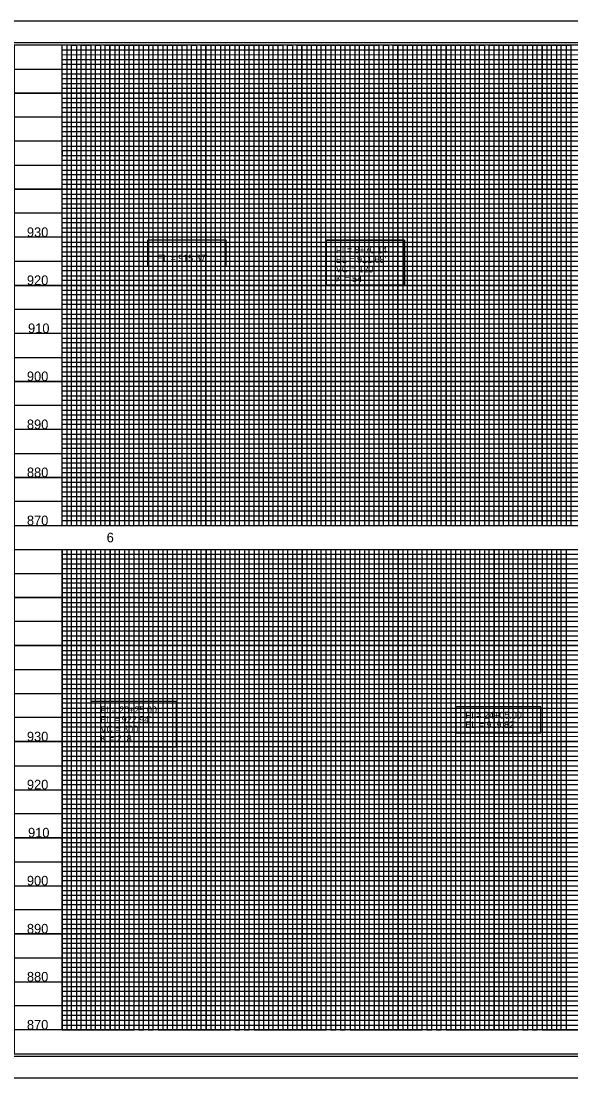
# Model space of a CAD drawing. Extents: x 1648157 to 1650776, y 832691 to 834781.
# Drawn here: x 1649037 to 1649609, y 832691 to 833791 of the extents above; entities that cross this region are included whole.
import ezdxf

# ---------------------------------------------------------------- set-up
doc = ezdxf.new("R2010")
doc.units = 0
for name, color, linetype in [('Exist Vertical Profile Horizontal Axis Label Major', 7, 'Continuous'), ('Exist Vertical Profile Vertical Axis Label', 7, 'Continuous'), ('Prop Grid Mask', 7, 'Continuous'), ('Prop Vertical Profile Curve Label', 7, 'Continuous'), ('Prop VPI Label', 7, 'Continuous'), ('Sheet Cutting Line CELL', 7, 'Continuous'), ('Sheet DOT Grid CELL', 7, 'Continuous'), ('Sheet Layout Profile Border Port 2', 7, 'Continuous'), ('Sheet Plot Border Inside CELL', 7, 'Continuous'), ('Sheet Plot Border Outside CELL', 7, 'Continuous'), ('Sheet Profile CELL', 7, 'Continuous'), ('Sheet Profile Grid Major CELL', 7, 'Continuous'), ('Sheet Profile Grid Middle CELL', 7, 'Continuous'), ('Sheet Profile Grid Minor CELL', 7, 'Continuous')]:
    doc.layers.add(name, color=color, linetype=linetype)

msp = doc.modelspace()

# ---------------------------------------------------------------- linework, layer by layer
at = {"layer": 'Prop Grid Mask'}
for points in [[(1649168.2, 833563), (1649168.2, 833536), (1649250.2, 833536), (1649250.2, 833563)], [(1649354.3, 833563.1), (1649436, 833563.1), (1649436, 833516.1), (1649354.3, 833516.1)], [(1649354.3, 833563.1), (1649354.3, 833516.1), (1649436, 833516.1), (1649436, 833563.1)], [(1649109.3, 833082.7), (1649109.3, 833035.7), (1649198.5, 833035.7), (1649198.5, 833082.7)], [(1649489.3, 833077.1), (1649489.3, 833050.1), (1649577.8, 833050.1), (1649577.8, 833077.1)]]:
    msp.add_lwpolyline(points, close=True, dxfattribs=at)
at = {"layer": 'Sheet Cutting Line CELL'}
for p, q in [((1650546.3, 833791), (1648862.3, 833791)), ((1648862.3, 832691), (1650546.3, 832691))]:
    msp.add_line(p, q, dxfattribs=at)
at = {"layer": 'Sheet DOT Grid CELL'}
for p, q in [((1649079.3, 833266), (1649079.3, 833766)), ((1649129.3, 833266), (1649129.3, 833766)), ((1649179.3, 833266), (1649179.3, 833766)), ((1649229.3, 833266), (1649229.3, 833766)), ((1649279.3, 833266), (1649279.3, 833766)), ((1649329.3, 833266), (1649329.3, 833766)), ((1649379.3, 833266), (1649379.3, 833766)), ((1649429.3, 833266), (1649429.3, 833766)), ((1649479.3, 833266), (1649479.3, 833766)), ((1649529.3, 833266), (1649529.3, 833766)), ((1649579.3, 833266), (1649579.3, 833766)), ((1650329.2, 833716), (1649029.3, 833716)), ((1650329.2, 833666), (1649029.3, 833666)), ((1650329.3, 833616), (1649029.3, 833616)), ((1650529.3, 833566), (1649029.3, 833566)), ((1650529.3, 833516), (1649029.3, 833516)), ((1650529.3, 833466), (1649029.3, 833466)), ((1650529.3, 833416), (1649029.3, 833416)), ((1650529.3, 833366), (1649029.3, 833366)), ((1650529.3, 833316), (1649029.3, 833316)), ((1649029.3, 833241), (1650529.2, 833241)), ((1649079.3, 833241), (1649079.3, 832741)), ((1649129.3, 833241), (1649129.3, 832741)), ((1649179.3, 833241), (1649179.3, 832741)), ((1649229.3, 833241), (1649229.3, 832741)), ((1649279.3, 833241), (1649279.3, 832741)), ((1649329.3, 833241), (1649329.3, 832741)), ((1649379.3, 833241), (1649379.3, 832741)), ((1649429.3, 833241), (1649429.3, 832741)), ((1649479.3, 833241), (1649479.3, 832741)), ((1649529.3, 833241), (1649529.3, 832741)), ((1649579.3, 833241), (1649579.3, 832741)), ((1649029.3, 833191), (1650529.2, 833191)), ((1649029.3, 833141), (1650529.2, 833141)), ((1649029.3, 833091), (1650529.2, 833091)), ((1649029.3, 833041), (1650529.2, 833041)), ((1649029.3, 832991), (1650529.2, 832991)), ((1649029.3, 832941), (1650529.2, 832941)), ((1649029.3, 832891), (1650529.2, 832891)), ((1649029.3, 832841), (1650529.2, 832841)), ((1649029.3, 832791), (1650529.2, 832791))]:
    msp.add_line(p, q, dxfattribs=at)
at = {"layer": 'Sheet Layout Profile Border Port 2'}
msp.add_lwpolyline([(1649079.3, 833241), (1650479.3, 833241), (1650479.3, 832741), (1649079.3, 832741)], close=True, dxfattribs=at)
at = {"layer": 'Sheet Plot Border Inside CELL'}
msp.add_lwpolyline([(1648875.3, 832713.5), (1650541.8, 832713.5), (1650541.8, 833768.6), (1648875.3, 833768.6)], close=True, dxfattribs=at)
at = {"layer": 'Sheet Plot Border Outside CELL'}
msp.add_lwpolyline([(1648862.3, 832691), (1650546.3, 832691), (1650546.3, 833791), (1648862.3, 833791)], close=True, dxfattribs=at)
at = {"layer": 'Sheet Profile CELL'}
for p, q in [((1649029.3, 833266), (1650529.3, 833266)), ((1649029.3, 833241), (1650529.3, 833241)), ((1650529.3, 832741), (1649029.3, 832741)), ((1649029.3, 832716), (1650529.3, 832716))]:
    msp.add_line(p, q, dxfattribs=at)
msp.add_lwpolyline([(1650529.3, 833766), (1649029.3, 833766), (1649029.3, 832716), (1650529.3, 832716)], close=True, dxfattribs=at)
msp.add_lwpolyline([(1649066.8, 832716), (1649066.8, 832716)], dxfattribs=at)
at = {"layer": 'Sheet Profile Grid Major CELL'}
msp.add_line((1649529.3, 833241), (1649579.3, 833241), dxfattribs=at)
for points in [[(1649079.2, 833766), (1649079.2, 833266), (1649129.2, 833266), (1649129.2, 833766), (1649179.2, 833766), (1649179.2, 833266), (1649229.2, 833266), (1649229.2, 833766), (1649279.2, 833766), (1649279.2, 833266), (1649329.2, 833266), (1649329.2, 833766), (1649379.2, 833766), (1649379.2, 833266), (1649429.2, 833266), (1649429.2, 833766), (1649479.2, 833766), (1649479.2, 833266), (1649529.2, 833266), (1649529.2, 833766), (1649579.2, 833766), (1649579.2, 833266), (1649629.2, 833266)], [(1649029.2, 833716), (1650329.2, 833716)], [(1650329.2, 833666), (1649029.2, 833666), (1649029.2, 833616), (1650329.2, 833616)], [(1650529.2, 833566), (1649029.2, 833566), (1649029.2, 833516), (1650529.2, 833516)], [(1650529.2, 833466), (1649029.2, 833466), (1649029.2, 833416), (1650529.2, 833416)], [(1650529.2, 833366), (1649029.2, 833366), (1649029.2, 833366), (1649029.2, 833316), (1650529.2, 833316)], [(1649079.3, 833241), (1649079.3, 832741), (1649129.3, 832741), (1649129.3, 833241), (1649179.3, 833241), (1649179.3, 832741), (1649229.3, 832741), (1649229.3, 833241), (1649279.3, 833241), (1649279.3, 832741), (1649329.3, 832741), (1649329.3, 833241), (1649379.3, 833241), (1649379.3, 832741), (1649429.3, 832741), (1649429.3, 833241), (1649479.3, 833241), (1649479.3, 832741), (1649529.3, 832741), (1649529.3, 833241), (1649579.3, 833241), (1649579.3, 832741), (1649629.3, 832741)], [(1650529.3, 833191), (1649029.3, 833191)], [(1650529.3, 833141), (1649029.3, 833141), (1649029.3, 833091), (1650529.3, 833091)], [(1650529.3, 833041), (1649029.3, 833041), (1649029.3, 832991), (1650529.3, 832991)], [(1650529.3, 832941), (1649029.3, 832941), (1649029.3, 832891), (1650529.3, 832891)], [(1650529.3, 832841), (1649029.3, 832841), (1649029.3, 832841), (1649029.3, 832791), (1650529.3, 832791)], [(1650529.3, 832741), (1649029.3, 832741)]]:
    msp.add_lwpolyline(points, dxfattribs=at)
at = {"layer": 'Sheet Profile Grid Middle CELL'}
msp.add_line((1649029.2, 833741), (1650179.2, 833741), dxfattribs=at)
for points in [[(1649104.2, 833766), (1649104.2, 833266), (1649154.2, 833266), (1649154.2, 833766), (1649204.2, 833766), (1649204.2, 833266), (1649254.2, 833266), (1649254.2, 833766), (1649304.2, 833766), (1649304.2, 833266), (1649354.2, 833266), (1649354.2, 833766), (1649404.2, 833766), (1649404.2, 833266), (1649454.2, 833266), (1649454.2, 833766), (1649504.2, 833766), (1649504.2, 833266), (1649554.2, 833266), (1649554.2, 833766), (1649604.2, 833766), (1649604.2, 833266), (1649654.2, 833266)], [(1650329.2, 833691), (1649029.2, 833691), (1649029.2, 833641), (1650329.2, 833641)], [(1650529.2, 833591), (1649029.2, 833591), (1649029.2, 833541), (1650354.2, 833541)], [(1650529.2, 833491), (1649029.2, 833491), (1649029.2, 833441), (1650529.2, 833441)], [(1650529.2, 833391), (1649029.2, 833391), (1649029.2, 833341), (1650529.2, 833341)], [(1650529.2, 833291), (1649029.2, 833291)], [(1649054.3, 833241), (1649104.3, 833241), (1649104.3, 832741), (1649154.3, 832741), (1649154.3, 833241), (1649204.3, 833241), (1649204.3, 832741), (1649254.3, 832741), (1649254.3, 833241), (1649304.3, 833241), (1649304.3, 832741), (1649354.3, 832741), (1649354.3, 833241), (1649404.3, 833241), (1649404.3, 832741), (1649454.3, 832741), (1649454.3, 833241), (1649504.3, 833241), (1649504.3, 832741), (1649554.3, 832741), (1649554.3, 833241), (1649604.3, 833241), (1649604.3, 832741), (1649654.3, 832741)], [(1649029.3, 833216), (1650529.3, 833216)], [(1650529.3, 833166), (1649029.3, 833166), (1649029.3, 833116), (1650529.3, 833116)], [(1650529.3, 833066), (1649029.3, 833066), (1649029.3, 833016), (1650529.3, 833016)], [(1650529.3, 832966), (1649029.3, 832966), (1649029.3, 832916), (1650529.3, 832916)], [(1650529.3, 832866), (1649029.3, 832866), (1649029.3, 832816), (1650529.3, 832816)], [(1650529.3, 832766), (1649029.3, 832766)]]:
    msp.add_lwpolyline(points, dxfattribs=at)
at = {"layer": 'Sheet Profile Grid Minor CELL'}
for p, q in [((1649079.2, 833761), (1650179.2, 833761)), ((1649079.2, 833756), (1649079.2, 833756)), ((1649079.2, 833756), (1649079.2, 833756)), ((1649079.2, 833756), (1649079.2, 833756)), ((1649079.3, 833756), (1649079.3, 833756)), ((1650179.2, 833756), (1649079.2, 833755.7)), ((1649079.2, 833751), (1650179.2, 833751)), ((1650329.2, 833631), (1649079.2, 833631)), ((1650329.2, 833626), (1649079.2, 833626)), ((1650329.2, 833621), (1649079.2, 833621)), ((1649079.2, 833611), (1650329.2, 833611)), ((1650329.2, 833606), (1649079.2, 833606)), ((1649079.2, 833601), (1650479.2, 833601)), ((1650479.2, 833581), (1649079.2, 833581)), ((1649079.2, 833576), (1650479.2, 833576)), ((1650479.2, 833556), (1649079.2, 833556)), ((1649079.2, 833551), (1650479.2, 833551)), ((1650479.2, 833531), (1649079.2, 833531)), ((1649079.2, 833526), (1650479.2, 833526)), ((1650479.2, 833521), (1649079.2, 833521)), ((1649079.2, 833511), (1650479.2, 833511)), ((1650479.2, 833506), (1649079.2, 833506)), ((1649079.2, 833501), (1650479.2, 833501)), ((1650479.2, 833496), (1649079.2, 833496)), ((1649079.2, 833486), (1650479.2, 833486)), ((1650479.2, 833481), (1649079.2, 833481)), ((1649079.2, 833476), (1650479.2, 833476)), ((1650479.2, 833471), (1649079.2, 833471)), ((1649079.2, 833461), (1650479.2, 833461)), ((1650479.2, 833456), (1649079.2, 833456)), ((1649079.2, 833451), (1650479.2, 833451)), ((1650479.2, 833446), (1649079.2, 833446)), ((1649079.2, 833436), (1650479.2, 833436)), ((1650479.2, 833431), (1649079.2, 833431)), ((1649079.2, 833426), (1650479.2, 833426)), ((1650479.2, 833421), (1649079.2, 833421)), ((1649079.2, 833411), (1650479.2, 833411)), ((1650479.2, 833406), (1649079.2, 833406)), ((1649079.2, 833401), (1650479.2, 833401)), ((1650479.2, 833396), (1649079.2, 833396)), ((1649079.2, 833386), (1650479.2, 833386)), ((1650479.2, 833381), (1649079.2, 833381)), ((1650479.2, 833376), (1649079.2, 833376)), ((1650479.2, 833371), (1649079.2, 833371)), ((1649079.2, 833361), (1650479.2, 833361)), ((1650479.2, 833356), (1649079.2, 833356)), ((1649079.2, 833351), (1650479.2, 833351)), ((1650479.2, 833346), (1649079.2, 833346)), ((1649079.2, 833336), (1650479.2, 833336)), ((1650479.2, 833331), (1649079.2, 833331)), ((1649079.2, 833326), (1650479.2, 833326)), ((1650479.2, 833321), (1649079.2, 833321)), ((1649079.2, 833311), (1650479.2, 833311)), ((1650479.2, 833306), (1649079.2, 833306)), ((1649079.2, 833301), (1650479.2, 833301)), ((1650479.2, 833296), (1649079.2, 833296)), ((1649079.2, 833286), (1650479.2, 833286)), ((1650479.2, 833281), (1649079.2, 833281)), ((1649079.2, 833276), (1650479.2, 833276)), ((1649079.3, 833236), (1650479.3, 833236)), ((1650479.3, 833231), (1649079.3, 833231)), ((1649079.3, 833226), (1650479.3, 833226)), ((1650479.3, 833221), (1649079.3, 833221)), ((1649079.3, 833211), (1650479.3, 833211)), ((1650479.3, 833206), (1649079.3, 833206)), ((1649079.3, 833201), (1650479.3, 833201)), ((1650479.3, 833196), (1649079.3, 833196)), ((1649079.3, 833186), (1650479.3, 833186)), ((1650479.3, 833181), (1649079.3, 833181)), ((1649079.3, 833176), (1650479.3, 833176)), ((1650479.3, 833171), (1649079.3, 833171)), ((1649079.3, 833161), (1650479.3, 833161)), ((1650479.3, 833156), (1649079.3, 833156)), ((1649079.3, 833151), (1650479.3, 833151)), ((1650479.3, 833146), (1649079.3, 833146)), ((1649079.3, 833136), (1650479.3, 833136)), ((1650479.3, 833131), (1649079.3, 833131)), ((1649079.3, 833126), (1650479.3, 833126)), ((1650479.3, 833121), (1649079.3, 833121)), ((1649079.3, 833111), (1650479.3, 833111)), ((1650479.3, 833106), (1649079.3, 833106)), ((1649079.3, 833101), (1650479.3, 833101)), ((1650479.3, 833096), (1649079.3, 833096)), ((1649079.3, 833086), (1650479.3, 833086)), ((1650479.3, 833081), (1649079.3, 833081)), ((1649079.3, 833076), (1650479.3, 833076)), ((1650479.3, 833071), (1649079.3, 833071)), ((1649079.3, 833061), (1650479.3, 833061)), ((1650479.3, 833056), (1649079.3, 833056)), ((1649079.3, 833051), (1650479.3, 833051)), ((1650479.3, 833046), (1649079.3, 833046.2)), ((1649079.3, 833036), (1650479.3, 833036)), ((1650479.3, 833031), (1649079.3, 833031)), ((1649079.3, 833026), (1650479.3, 833026)), ((1650479.3, 833021), (1649079.3, 833021)), ((1649079.3, 833011), (1650479.3, 833011)), ((1650479.3, 833006), (1649079.3, 833006)), ((1649079.3, 833001), (1650479.3, 833001)), ((1650479.3, 832996), (1649079.3, 832996)), ((1649079.3, 832986), (1650479.3, 832986)), ((1650479.3, 832981), (1649079.3, 832981)), ((1649079.3, 832976), (1650479.3, 832976)), ((1650479.3, 832971), (1649079.3, 832971)), ((1649079.3, 832961), (1650479.3, 832961)), ((1650479.3, 832956), (1649079.3, 832956)), ((1649079.3, 832951), (1650479.3, 832951)), ((1650479.3, 832946), (1649079.3, 832946)), ((1649079.3, 832936), (1650479.3, 832936)), ((1650479.3, 832931), (1649079.3, 832931)), ((1649079.3, 832926), (1650479.3, 832926)), ((1650479.3, 832921), (1649079.3, 832921)), ((1649079.3, 832911), (1650479.3, 832911)), ((1650479.3, 832906), (1649079.3, 832906)), ((1649079.3, 832901), (1650479.3, 832901)), ((1650479.3, 832896), (1649079.3, 832896)), ((1649079.3, 832886), (1650479.3, 832886)), ((1650479.3, 832881), (1649079.3, 832881)), ((1649079.3, 832876), (1650479.3, 832876)), ((1650479.3, 832871), (1649079.3, 832871)), ((1649079.3, 832861), (1650479.3, 832861)), ((1650479.3, 832856), (1649079.3, 832856)), ((1649079.3, 832851), (1650479.3, 832851)), ((1650479.3, 832846), (1649079.3, 832846)), ((1649079.3, 832836), (1650479.3, 832836)), ((1650479.3, 832831), (1649079.3, 832831)), ((1649079.3, 832826), (1650479.3, 832826)), ((1650479.3, 832821), (1649079.3, 832821)), ((1649079.3, 832811), (1650479.3, 832811)), ((1650479.3, 832806), (1649079.3, 832806)), ((1649079.3, 832801), (1650479.3, 832801)), ((1650479.3, 832796), (1649079.3, 832796)), ((1649079.3, 832786), (1650479.3, 832786)), ((1650479.3, 832781), (1649079.3, 832781)), ((1649079.3, 832776), (1650479.3, 832776)), ((1650479.3, 832771), (1649079.3, 832771)), ((1649079.3, 832761), (1650479.3, 832761)), ((1650479.3, 832756), (1649079.3, 832756)), ((1649079.3, 832751), (1650479.3, 832751)), ((1649079.3, 832746), (1650479.3, 832746))]:
    msp.add_line(p, q, dxfattribs=at)
for points in [[(1649084.2, 833766), (1649084.2, 833266), (1649089.2, 833266), (1649089.2, 833766), (1649094.2, 833766), (1649094.2, 833266), (1649099.2, 833266), (1649099.2, 833766), (1649109.2, 833766), (1649109.2, 833266), (1649114.2, 833266), (1649114.2, 833766), (1649119.2, 833766), (1649119.2, 833266), (1649124.2, 833266), (1649134.2, 833266), (1649139.2, 833266), (1649139.2, 833766), (1649144.2, 833766), (1649144.2, 833266), (1649149.2, 833266), (1649149.2, 833766), (1649159.2, 833766), (1649159.2, 833266), (1649164.2, 833266), (1649164.2, 833766), (1649169.2, 833766), (1649169.2, 833266), (1649174.2, 833266), (1649174.2, 833766), (1649184.2, 833766), (1649184.2, 833266), (1649189.2, 833266), (1649189.2, 833766), (1649194.2, 833766), (1649194.2, 833266), (1649199.2, 833266), (1649199.2, 833766), (1649209.2, 833766), (1649209.2, 833266), (1649214.2, 833266), (1649214.2, 833766), (1649219.2, 833766), (1649219.2, 833266), (1649224.2, 833266), (1649224.2, 833766), (1649234.2, 833766), (1649234.2, 833266), (1649239.2, 833266), (1649239.2, 833766), (1649244.2, 833766), (1649244.2, 833266), (1649249.2, 833266), (1649249.2, 833766), (1649259.2, 833766), (1649259.2, 833266), (1649264.2, 833266), (1649264.2, 833766), (1649269.2, 833766), (1649269.2, 833266), (1649274.2, 833266), (1649274.2, 833766), (1649284.2, 833766), (1649284.2, 833266), (1649289.2, 833266), (1649289.2, 833766), (1649294.2, 833766), (1649294.2, 833266)], [(1649124.2, 833266), (1649124.2, 833766), (1649134.2, 833766), (1649134.2, 833266)], [(1649294.2, 833266), (1649299.2, 833266), (1649299.2, 833766), (1649309.2, 833766), (1649309.2, 833266), (1649314.2, 833266), (1649314.2, 833766), (1649319.2, 833766), (1649319.2, 833266), (1649324.2, 833266), (1649324.2, 833766), (1649334.2, 833766), (1649334.2, 833266), (1649339.2, 833266), (1649339.2, 833766), (1649344.2, 833766), (1649344.2, 833266), (1649349.2, 833266), (1649349.2, 833766), (1649359.2, 833766), (1649359.2, 833266), (1649364.2, 833266), (1649364.2, 833766), (1649369.2, 833766), (1649369.2, 833266), (1649374.2, 833266), (1649374.2, 833766), (1649384.2, 833766), (1649384.2, 833266), (1649389.2, 833266), (1649389.2, 833766), (1649394.2, 833766), (1649394.2, 833266), (1649399.2, 833266), (1649399.2, 833766), (1649409.2, 833766), (1649409.2, 833266), (1649414.2, 833266), (1649414.2, 833766), (1649419.2, 833766), (1649419.2, 833266), (1649424.2, 833266), (1649424.2, 833766), (1649434.2, 833766), (1649434.2, 833266), (1649439.2, 833266), (1649439.2, 833766), (1649444.2, 833766), (1649444.2, 833266), (1649449.2, 833266), (1649449.2, 833766), (1649459.2, 833766), (1649459.2, 833266), (1649464.2, 833266), (1649464.2, 833766), (1649469.2, 833766), (1649469.2, 833266), (1649474.2, 833266), (1649474.2, 833766), (1649484.2, 833766), (1649484.2, 833266), (1649489.2, 833266), (1649489.2, 833766), (1649494.2, 833766), (1649494.2, 833266), (1649499.2, 833266), (1649499.2, 833766), (1649509.2, 833766), (1649509.2, 833266), (1649514.2, 833266), (1649514.2, 833766), (1649519.2, 833766), (1649519.2, 833266), (1649524.2, 833266), (1649524.2, 833766), (1649534.2, 833766), (1649534.2, 833266), (1649539.2, 833266), (1649539.2, 833766), (1649544.2, 833766), (1649544.2, 833266), (1649549.2, 833266), (1649549.2, 833766), (1649559.2, 833766), (1649559.2, 833266), (1649564.2, 833266), (1649564.2, 833766), (1649569.2, 833766), (1649569.2, 833266), (1649574.2, 833266), (1649574.2, 833766), (1649584.2, 833766), (1649584.2, 833266), (1649589.2, 833266), (1649589.2, 833766), (1649594.2, 833766), (1649594.2, 833266), (1649599.2, 833266), (1649599.2, 833766), (1649609.2, 833766)], [(1649609.2, 833766), (1649609.2, 833266), (1649614.2, 833266)], [(1650179.2, 833746), (1649079.2, 833746), (1649079.2, 833736), (1650329.2, 833736)], [(1650329.2, 833731), (1649079.2, 833731), (1649079.2, 833726), (1650329.2, 833726)], [(1650329.2, 833721), (1649079.2, 833721), (1649079.2, 833711), (1650329.2, 833711)], [(1650329.2, 833706), (1649079.2, 833706), (1649079.2, 833701), (1650329.2, 833701)], [(1650329.2, 833696), (1649079.2, 833696), (1649079.2, 833686), (1650329.2, 833686)], [(1650329.2, 833681), (1649079.2, 833681), (1649079.2, 833676), (1650329.2, 833676)], [(1650329.2, 833671), (1649079.2, 833671), (1649079.2, 833661), (1650329.2, 833661)], [(1650329.2, 833646), (1649079.2, 833646), (1649079.2, 833636), (1650329.2, 833636)], [(1650329.2, 833655.9), (1649079.3, 833655.9), (1649079.3, 833651), (1650329.2, 833651)], [(1650479.2, 833596), (1649079.2, 833596), (1649079.2, 833586), (1650479.2, 833586)], [(1650479.2, 833571), (1649079.2, 833571), (1649079.2, 833561), (1650479.2, 833561)], [(1650479.2, 833546), (1649079.2, 833546), (1649079.2, 833536), (1650479.2, 833536)], [(1650479.2, 833271), (1649079.2, 833271)], [(1649079.3, 833241), (1649084.3, 833241), (1649084.3, 832741), (1649089.3, 832741), (1649089.3, 833241), (1649094.3, 833241), (1649094.3, 832741), (1649099.3, 832741), (1649099.3, 833241), (1649109.3, 833241), (1649109.3, 832741), (1649114.3, 832741), (1649114.3, 833241), (1649119.3, 833241), (1649119.3, 832741), (1649124.3, 832741), (1649134.3, 832741), (1649139.3, 832741), (1649139.3, 833241), (1649144.3, 833241), (1649144.3, 832741), (1649149.3, 832741), (1649149.3, 833241), (1649159.3, 833241), (1649159.3, 832741), (1649164.3, 832741), (1649164.3, 833241), (1649169.3, 833241), (1649169.3, 832741), (1649174.3, 832741), (1649174.3, 833241), (1649184.3, 833241), (1649184.3, 832741), (1649189.3, 832741), (1649189.3, 833241), (1649194.3, 833241), (1649194.3, 832741), (1649199.3, 832741), (1649199.3, 833241), (1649209.3, 833241), (1649209.3, 832741), (1649214.3, 832741), (1649214.3, 833241), (1649219.3, 833241), (1649219.3, 832741), (1649224.3, 832741), (1649224.3, 833241), (1649234.3, 833241), (1649234.3, 832741), (1649239.3, 832741), (1649239.3, 833241), (1649244.3, 833241), (1649244.3, 832741), (1649249.3, 832741), (1649249.3, 833241), (1649259.3, 833241), (1649259.3, 832741), (1649264.3, 832741), (1649264.3, 833241), (1649269.3, 833241), (1649269.3, 832741), (1649274.3, 832741), (1649274.3, 833241), (1649284.3, 833241), (1649284.3, 832741), (1649289.3, 832741), (1649289.3, 833241), (1649294.3, 833241), (1649294.3, 832741)], [(1649124.3, 832741), (1649124.3, 833241), (1649134.3, 833241), (1649134.3, 832741)], [(1649294.3, 832741), (1649299.3, 832741), (1649299.3, 833241), (1649309.3, 833241), (1649309.3, 832741), (1649314.3, 832741), (1649314.3, 833241), (1649319.3, 833241), (1649319.3, 832741), (1649324.3, 832741), (1649324.3, 833241), (1649334.3, 833241), (1649334.3, 832741), (1649339.3, 832741), (1649339.3, 833241), (1649344.3, 833241), (1649344.3, 832741), (1649349.3, 832741), (1649349.3, 833241), (1649359.3, 833241), (1649359.3, 832741), (1649364.3, 832741), (1649364.3, 833241), (1649369.3, 833241), (1649369.3, 832741), (1649374.3, 832741), (1649374.3, 833241), (1649384.3, 833241), (1649384.3, 832741), (1649389.3, 832741), (1649389.3, 833241), (1649394.3, 833241), (1649394.3, 832741), (1649399.3, 832741), (1649399.3, 833241), (1649409.3, 833241), (1649409.3, 832741), (1649414.3, 832741), (1649414.3, 833241), (1649419.3, 833241), (1649419.3, 832741), (1649424.3, 832741), (1649424.3, 833241), (1649434.3, 833241), (1649434.3, 832741), (1649439.3, 832741), (1649439.3, 833241), (1649444.3, 833241), (1649444.3, 832741), (1649449.3, 832741), (1649449.3, 833241), (1649459.3, 833241), (1649459.3, 832741), (1649464.3, 832741), (1649464.3, 833241), (1649469.3, 833241), (1649469.3, 832741), (1649474.3, 832741), (1649474.3, 833241), (1649484.3, 833241), (1649484.3, 832741), (1649489.3, 832741), (1649489.3, 833241), (1649494.3, 833241), (1649494.3, 832741), (1649499.3, 832741), (1649499.3, 833241), (1649509.3, 833241), (1649509.3, 832741), (1649514.3, 832741), (1649514.3, 833241), (1649519.3, 833241), (1649519.3, 832741), (1649524.3, 832741), (1649524.3, 833241), (1649534.3, 833241), (1649534.3, 832741), (1649539.3, 832741), (1649539.3, 833241), (1649544.3, 833241), (1649544.3, 832741), (1649549.3, 832741), (1649549.3, 833241), (1649559.3, 833241), (1649559.3, 832741), (1649564.3, 832741), (1649564.3, 833241), (1649569.3, 833241), (1649569.3, 832741), (1649574.3, 832741), (1649574.3, 833241), (1649584.3, 833241), (1649584.3, 832741), (1649589.3, 832741), (1649589.3, 833241), (1649594.3, 833241), (1649594.3, 832741), (1649599.3, 832741), (1649599.3, 833241), (1649609.3, 833241)]]:
    msp.add_lwpolyline(points, dxfattribs=at)

# ---------------------------------------------------------------- texts
at = {"layer": 'Exist Vertical Profile Horizontal Axis Label Major'}
msp.add_text('6', height=10, dxfattribs=at).set_placement((1649125.8, 833248.5))
at = {"layer": 'Exist Vertical Profile Vertical Axis Label'}
for s, p in [('930', (1649042.7, 833566.3)), ('920', (1649042.7, 833516.3)), ('910', (1649043.9, 833466.3)), ('900', (1649042.7, 833416.3)), ('890', (1649042.7, 833366.3)), ('880', (1649042.7, 833316.3)), ('870', (1649042.7, 833266.3)), ('930', (1649042.7, 833041.3)), ('920', (1649042.7, 832991.3)), ('910', (1649043.9, 832941.3)), ('900', (1649042.7, 832891.3)), ('890', (1649042.7, 832841.3)), ('880', (1649042.7, 832791.3)), ('870', (1649042.7, 832741.3))]:
    msp.add_text(s, height=10, dxfattribs=at).set_placement(p)
at = {"layer": 'Prop Vertical Profile Curve Label'}
for s, p in [("VC = 120'", (1649364.4, 833529.4)), ('K = 54', (1649364.4, 833519.4)), ("VC = 300'", (1649119.3, 833050.7)), ('K = 218', (1649119.3, 833040.7))]:
    msp.add_text(s, height=7, dxfattribs=at).set_placement(p)
at = {"layer": 'Prop VPI Label'}
for s, p in [("EL = 915.37'", (1649178.2, 833541)), ("EL = 915.37'", (1649178.2, 833541)), ('PI = 8+70.14', (1649364.4, 833549.4)), ("EL = 911.68'", (1649364.4, 833539.4)), ('PI = 20+25.00', (1649119.3, 833070.7)), ("EL = 922.94'", (1649119.3, 833060.7)), ('PI = 24+05.00', (1649499.3, 833065.1)), ("EL = 919.82'", (1649499.3, 833055.1))]:
    msp.add_text(s, height=7, dxfattribs=at).set_placement(p)

doc.saveas('drawing.dxf')
